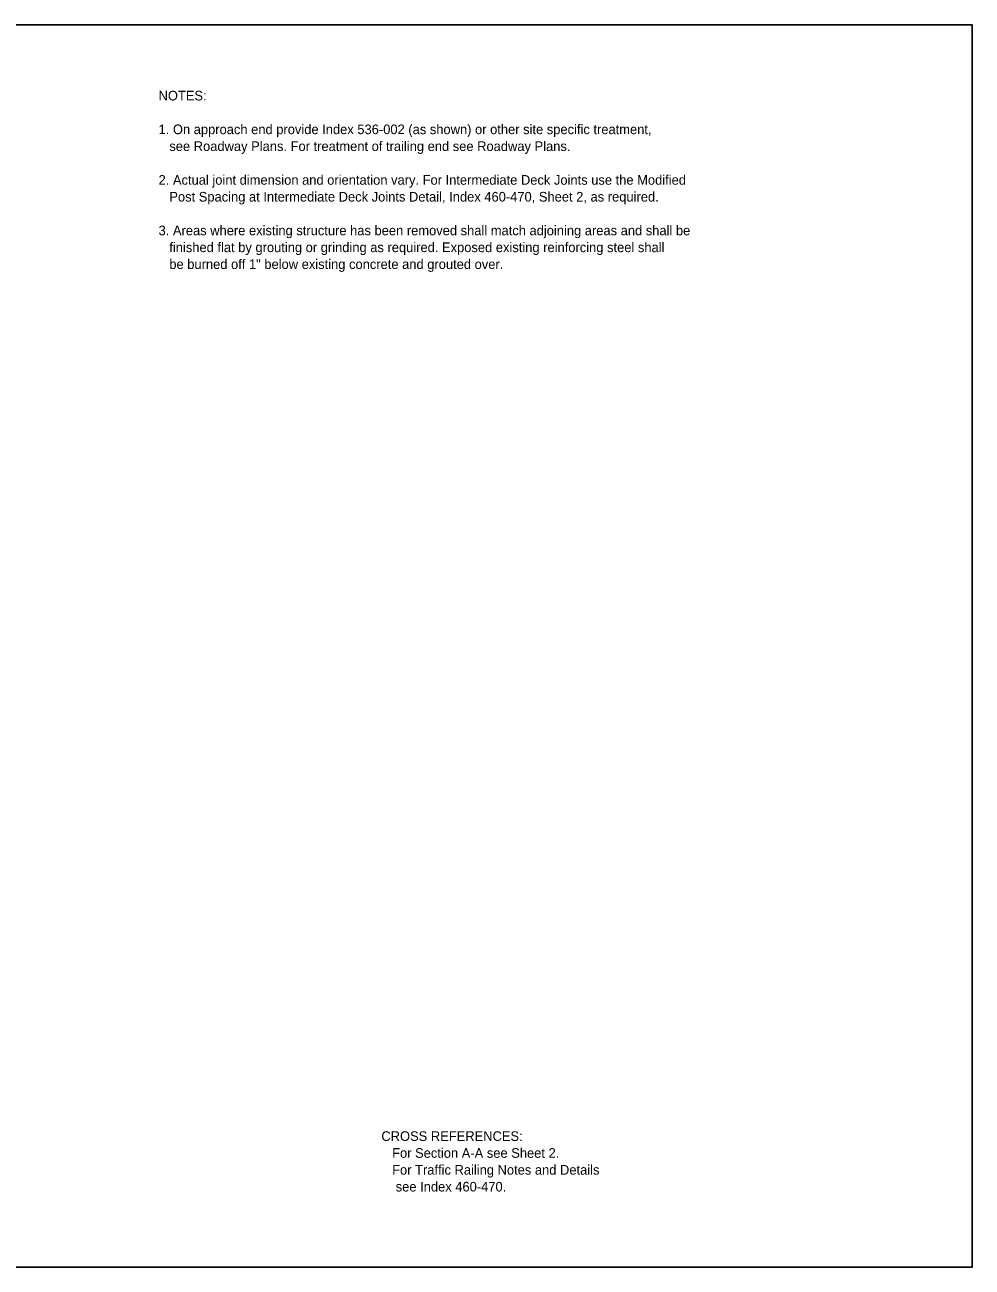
# Model space of a CAD drawing. Extents: x 0 to 41.1, y 0 to 25.9.
# Drawn here: x 21.27 to 41.05, y 0 to 25.95 of the extents above; entities that cross this region are included whole.
import ezdxf

# ---------------------------------------------------------------- set-up
doc = ezdxf.new("R2010")
doc.units = 0
for name, color, linetype in [('Dimension', 7, 'Continuous'), ('Miscellaneous1', 7, 'Continuous'), ('TextStructures', 7, 'Continuous')]:
    doc.layers.add(name, color=color, linetype=linetype)

msp = doc.modelspace()

# ---------------------------------------------------------------- linework, layer by layer
at = {"layer": 'Miscellaneous1'}
msp.add_lwpolyline([(0, 25.946), (41.051, 25.946), (41.051, 0), (0, 0)], close=True, dxfattribs=at)
at = {"layer": 'TextStructures'}
msp.add_lwpolyline([(0, 0), (41.051, 0), (41.051, 25.946), (0, 25.946)], close=True, dxfattribs=at)

# ---------------------------------------------------------------- texts
at = {"layer": 'Dimension'}
for s, p in [('NOTES:', (24.06, 24.367)), ('1. On approach end provide Index 536-002 (as shown) or other site specific treatment, ', (24.06, 23.663)), ('   see Roadway Plans. For treatment of trailing end see Roadway Plans.', (24.06, 23.311)), ('2. Actual joint dimension and orientation vary. For Intermediate Deck Joints use the Modified ', (24.06, 22.607)), ('   Post Spacing at Intermediate Deck Joints Detail, Index 460-470, Sheet 2, as required.', (24.06, 22.255)), ('3. Areas where existing structure has been removed shall match adjoining areas and shall be ', (24.06, 21.551)), ('   finished flat by grouting or grinding as required. Exposed existing reinforcing steel shall ', (24.06, 21.199)), ('   be burned off 1" below existing concrete and grouted over.', (24.06, 20.847)), ('CROSS REFERENCES:', (28.713, 2.636)), ('   For Section A-A see Sheet 2.', (28.713, 2.284)), ('   For Traffic Railing Notes and Details ', (28.713, 1.932)), ('    see Index 460-470.', (28.713, 1.58))]:
    msp.add_text(s, height=0.2016, dxfattribs=at).set_placement(p)

doc.saveas('drawing.dxf')
